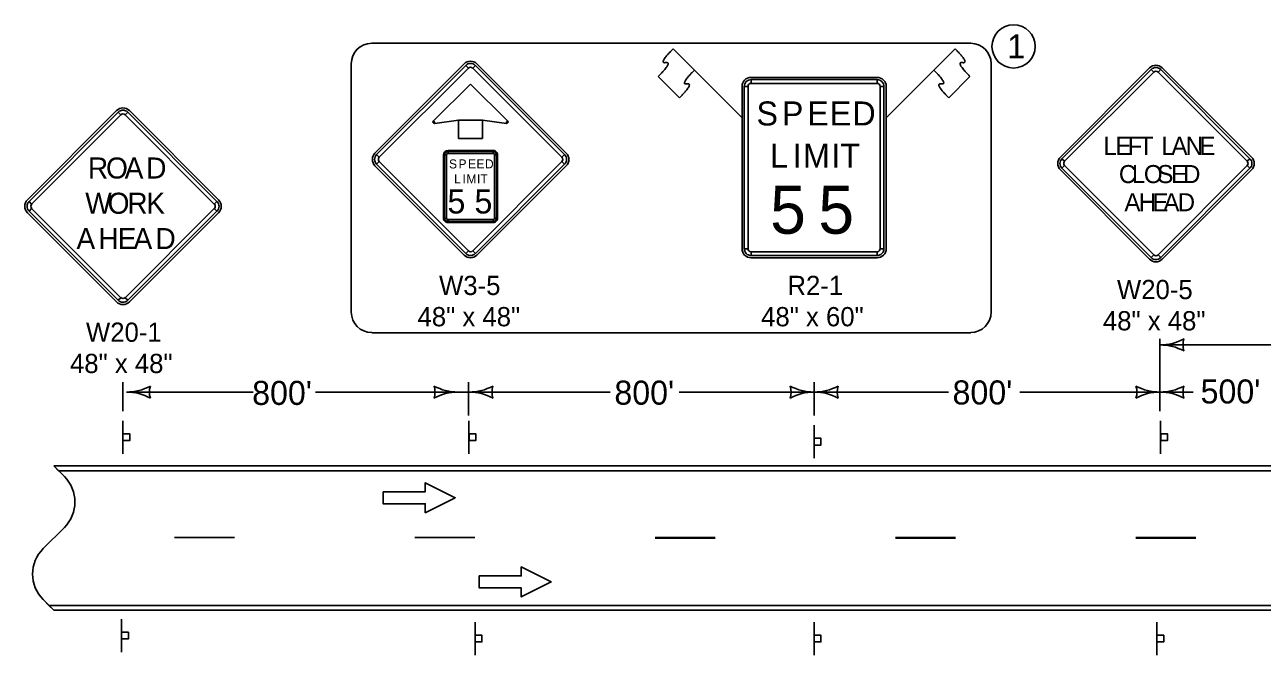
# Model space of a CAD drawing. Extents: x 10133 to 2270741, y 5363 to 1733450.
# Drawn here: x 24538 to 25567, y 6634 to 7159 of the extents above; entities that cross this region are included whole.
import ezdxf

# ---------------------------------------------------------------- set-up
doc = ezdxf.new("R2010")
doc.units = 0
for name, color, linetype in [('dsnNonPlotable', 7, 'Continuous'), ('dsnShtPlotShapeBatchPrint', 7, 'Continuous'), ('dsnStdBorder', 7, 'Continuous'), ('Level 12', 7, 'Continuous'), ('Level 2', 7, 'Continuous')]:
    doc.layers.add(name, color=color, linetype=linetype)

msp = doc.modelspace()

# ---------------------------------------------------------------- linework, layer by layer
at = {"layer": 'dsnNonPlotable'}
for p, q in [((24570.6, 6783), (24561.8, 6791.8)), ((24565.8, 6787.8), (26174.1, 6787.8)), ((24553, 6723), (24570.6, 6740.6)), ((24561.8, 6671.8), (24553, 6680.6)), ((24557.8, 6675.8), (26586.2, 6675.8))]:
    msp.add_line(p, q, dxfattribs=at)
for points in [[(24662.2, 6732.2), (24712.2, 6732.2)], [(24862.2, 6732.2), (24912.1, 6732.2)], [(25062.1, 6732.2), (25112.1, 6732.2)], [(25062.1, 6731.8), (25112.1, 6731.8)], [(25262.1, 6732.2), (25312.1, 6732.2)], [(25262.1, 6731.8), (25312.1, 6731.8)], [(25462.1, 6732.2), (25512.1, 6732.2)], [(25462.1, 6731.8), (25512.1, 6731.8)]]:
    msp.add_lwpolyline(points, dxfattribs=at)
for centre, start, end in [((24549.4, 6761.8), 315, 45), ((24574.2, 6701.8), 135, 225)]:
    msp.add_arc(centre, 30, start, end, dxfattribs=at)
at = {"layer": 'dsnShtPlotShapeBatchPrint'}
msp.add_circle((25360.5, 7140.7), 18, dxfattribs=at)
at = {"layer": 'dsnStdBorder'}
for p, q in [((25134.5, 7081.4), (25077.2, 7138.7)), ((25077.2, 7138.7), (25094.9, 7121)), ((25254.5, 7081.4), (25311.8, 7138.7)), ((25311.8, 7138.7), (25294.1, 7121)), ((24903.3, 7126.2), (24829.1, 7052)), ((24988.2, 7052), (24913.9, 7126.2)), ((24904.6, 7124.9), (24906.8, 7122.7)), ((24910.4, 7122.7), (24912.6, 7124.9)), ((25064.8, 7115.7), (25082.5, 7098)), ((25082.5, 7098), (25064.8, 7115.7)), ((25324.2, 7115.7), (25306.5, 7098)), ((25306.5, 7098), (25324.2, 7115.7)), ((25473.6, 7122.8), (25399.4, 7048.6)), ((25474.9, 7121.5), (25477.1, 7119.3)), ((25480.7, 7119.3), (25482.9, 7121.5)), ((25558.5, 7048.6), (25484.2, 7122.8)), ((25134.5, 7107.4), (25134.5, 6972.4)), ((25136.4, 7107.4), (25139.5, 7107.4)), ((25247, 7114.9), (25142, 7114.9)), ((25142, 7109.9), (25142, 7113.1)), ((25247, 7113.1), (25247, 7109.9)), ((25249.5, 7107.4), (25252.6, 7107.4)), ((25254.5, 6972.4), (25254.5, 7107.4)), ((24614.1, 7087.3), (24539.9, 7013)), ((24615.4, 7085.9), (24617.6, 7083.7)), ((24621.2, 7083.7), (24623.4, 7085.9)), ((24699, 7013), (24624.7, 7087.3)), ((24878.6, 7077.9), (24877.7, 7078.8)), ((24878.8, 7076.7), (24878.6, 7077.9)), ((24938.6, 7077.9), (24938.5, 7076.7)), ((24939.5, 7078.8), (24938.6, 7077.9)), ((24927.4, 7054.2), (24889.9, 7054.2)), ((24832.6, 7048.5), (24830.4, 7050.7)), ((24830.4, 7042.7), (24832.6, 7044.9)), ((24886.1, 7050.4), (24886.1, 6997.9)), ((24887, 7050.4), (24888.6, 7050.4)), ((24889.9, 7051.7), (24889.9, 7053.2)), ((24927.4, 7053.2), (24927.4, 7051.7)), ((24928.6, 7050.4), (24930.2, 7050.4)), ((24931.1, 6997.9), (24931.1, 7050.4)), ((24986.8, 7050.7), (24984.6, 7048.5)), ((24984.6, 7044.9), (24986.8, 7042.7)), ((25402.9, 7045.1), (25400.7, 7047.3)), ((25557.1, 7047.3), (25554.9, 7045.1)), ((24829.1, 7041.4), (24903.3, 6967.1)), ((24913.9, 6967.1), (24988.2, 7041.4)), ((25399.4, 7038), (25473.6, 6963.7)), ((25400.7, 7039.3), (25402.9, 7041.5)), ((25484.2, 6963.7), (25558.5, 7038)), ((25554.9, 7041.5), (25557.1, 7039.3)), ((24539.9, 7002.4), (24614.1, 6928.2)), ((24543.4, 7009.5), (24541.2, 7011.7)), ((24541.2, 7003.7), (24543.4, 7005.9)), ((24624.7, 6928.2), (24699, 7002.4)), ((24697.6, 7011.7), (24695.4, 7009.5)), ((24695.4, 7005.9), (24697.6, 7003.7)), ((24888.6, 6997.9), (24887, 6997.9)), ((24889.9, 6995.1), (24889.9, 6996.7)), ((24889.9, 6994.2), (24927.4, 6994.2)), ((24927.4, 6996.7), (24927.4, 6995.1)), ((24930.2, 6997.9), (24928.6, 6997.9)), ((25139.5, 6972.4), (25136.4, 6972.4)), ((25252.6, 6972.4), (25249.5, 6972.4)), ((24906.8, 6970.7), (24904.6, 6968.5)), ((24912.6, 6968.5), (24910.4, 6970.7)), ((25142, 6966.8), (25142, 6969.9)), ((25142, 6964.9), (25247, 6964.9)), ((25247, 6969.9), (25247, 6966.8)), ((25477.1, 6967.3), (25474.9, 6965.1)), ((25482.9, 6965.1), (25480.7, 6967.3)), ((24617.6, 6931.7), (24615.4, 6929.5)), ((24623.4, 6929.5), (24621.2, 6931.7)), ((24619.4, 6829.3), (24619.4, 6801.8)), ((24907.3, 6829.3), (24907.3, 6801.8)), ((25482.8, 6829.3), (25482.8, 6801.8)), ((25194.5, 6825.6), (25194.5, 6798.1)), ((24618.1, 6664.4), (24618.1, 6636.9)), ((24912.4, 6661.8), (24912.4, 6634.3)), ((25194.5, 6661.8), (25194.5, 6634.3)), ((25479.7, 6661.8), (25479.7, 6634.3))]:
    msp.add_line(p, q, dxfattribs=at)
for points in [[(24826.4, 7143.3), (25324.8, 7143.3)], [(24809.4, 6919.7), (24809.4, 7126.3)], [(25341.9, 7126.3), (25341.9, 6919.7)], [(25324.8, 6902.6), (24826.4, 6902.6)], [(24835.9, 6770.3), (24835.9, 6760.3), (24870.9, 6760.3), (24870.9, 6752.8), (24895.9, 6765.3), (24870.9, 6777.8), (24870.9, 6770.3), (24835.9, 6770.3)], [(24915.8, 6700.3), (24915.8, 6690.3), (24950.8, 6690.3), (24950.8, 6682.8), (24975.8, 6695.3), (24950.8, 6707.8), (24950.8, 6700.3), (24915.8, 6700.3)]]:
    msp.add_lwpolyline(points, dxfattribs=at)
for points in [[(24904.6, 7124.9), (24830.4, 7050.7), (24832.6, 7048.5), (24906.8, 7122.7), (24904.6, 7124.9)], [(24986.8, 7050.7), (24912.6, 7124.9), (24910.4, 7122.7), (24984.6, 7048.5), (24986.8, 7050.7)], [(25474.9, 7121.5), (25400.7, 7047.3), (25402.9, 7045.1), (25477.1, 7119.3), (25474.9, 7121.5)], [(25557.1, 7047.3), (25482.9, 7121.5), (25480.7, 7119.3), (25554.9, 7045.1), (25557.1, 7047.3)], [(24908.6, 7109.2), (24877.7, 7078.8), (24878.6, 7077.9), (24878.8, 7076.7), (24898.6, 7079.2), (24918.6, 7079.2), (24938.5, 7076.7), (24938.6, 7077.9), (24939.5, 7078.8), (24908.6, 7109.2)], [(25136.4, 7107.4), (25136.4, 6972.4), (25139.5, 6972.4), (25139.5, 7107.4), (25136.4, 7107.4)], [(25247, 7113.1), (25142, 7113.1), (25142, 7109.9), (25247, 7109.9), (25247, 7113.1)], [(25252.6, 6972.4), (25252.6, 7107.4), (25249.5, 7107.4), (25249.5, 6972.4), (25252.6, 6972.4)], [(24615.4, 7085.9), (24541.2, 7011.7), (24543.4, 7009.5), (24617.6, 7083.7), (24615.4, 7085.9)], [(24697.6, 7011.7), (24623.4, 7085.9), (24621.2, 7083.7), (24695.4, 7009.5), (24697.6, 7011.7)], [(24918.6, 7064.2), (24898.6, 7064.2), (24898.6, 7079.2), (24918.6, 7079.2), (24918.6, 7064.2)], [(24830.4, 7042.7), (24904.6, 6968.5), (24906.8, 6970.7), (24832.6, 7044.9), (24830.4, 7042.7)], [(24887, 7050.4), (24887, 6997.9), (24888.6, 6997.9), (24888.6, 7050.4), (24887, 7050.4)], [(24927.4, 7053.2), (24889.9, 7053.2), (24889.9, 7051.7), (24927.4, 7051.7), (24927.4, 7053.2)], [(24912.6, 6968.5), (24986.8, 7042.7), (24984.6, 7044.9), (24910.4, 6970.7), (24912.6, 6968.5)], [(24930.2, 6997.9), (24930.2, 7050.4), (24928.6, 7050.4), (24928.6, 6997.9), (24930.2, 6997.9)], [(25400.7, 7039.3), (25474.9, 6965.1), (25477.1, 6967.3), (25402.9, 7041.5), (25400.7, 7039.3)], [(25482.9, 6965.1), (25557.1, 7039.3), (25554.9, 7041.5), (25480.7, 6967.3), (25482.9, 6965.1)], [(24541.2, 7003.7), (24615.4, 6929.5), (24617.6, 6931.7), (24543.4, 7005.9), (24541.2, 7003.7)], [(24623.4, 6929.5), (24697.6, 7003.7), (24695.4, 7005.9), (24621.2, 6931.7), (24623.4, 6929.5)], [(24889.9, 6995.1), (24927.4, 6995.1), (24927.4, 6996.7), (24889.9, 6996.7), (24889.9, 6995.1)], [(25142, 6966.8), (25247, 6966.8), (25247, 6969.9), (25142, 6969.9), (25142, 6966.8)], [(24619.4, 6812.9), (24619.4, 6818.5), (24625.1, 6818.5), (24625.1, 6812.9)], [(24907.4, 6812.9), (24907.4, 6818.5), (24913, 6818.5), (24913, 6812.9)], [(25482.9, 6812.9), (25482.9, 6818.5), (25488.5, 6818.5), (25488.5, 6812.9)], [(25194.6, 6809.1), (25194.6, 6814.8), (25200.2, 6814.8), (25200.2, 6809.1)], [(24618.2, 6647.9), (24618.2, 6653.5), (24623.9, 6653.5), (24623.9, 6647.9)], [(24912.5, 6645.4), (24912.5, 6651), (24918.1, 6651), (24918.1, 6645.4)], [(25194.6, 6645.4), (25194.6, 6651), (25200.2, 6651), (25200.2, 6645.4)], [(25479.8, 6645.4), (25479.8, 6651), (25485.4, 6651), (25485.4, 6645.4)]]:
    msp.add_lwpolyline(points, close=True, dxfattribs=at)
for centre, radius, start, end in [((24826.4, 7126.3), 17, 90, 180), ((25324.8, 7126.3), 17, 0, 90), ((24908.6, 7120.9), 7.5, 45, 134.9997), ((24908.6, 7120.9), 5.62, 45, 134.9997), ((24908.6, 7120.9), 2.5, 45, 134.9997), ((25478.9, 7117.5), 7.5, 45, 134.9997), ((25478.9, 7117.5), 5.62, 45, 134.9997), ((25478.9, 7117.5), 2.5, 45, 134.9997), ((25142, 7107.4), 7.5, 90.0002, 179.9998), ((25142, 7107.4), 5.62, 90.0002, 179.9998), ((25142, 7107.4), 2.5, 90.0002, 179.9998), ((25247, 7107.4), 7.5, 0, 90.0002), ((25247, 7107.4), 5.62, 0, 90.0002), ((25247, 7107.4), 2.5, 0, 90.0002), ((24619.4, 7082), 7.5, 45, 134.9997), ((24619.4, 7082), 5.62, 45, 134.9997), ((24619.4, 7082), 2.5, 45, 134.9997), ((24878.6, 7077.9), 1.25, 134.9997, 277.1529), ((24938.6, 7077.9), 1.25, 262.8473, 44.9998), ((24889.9, 7050.4), 3.75, 90.0002, 179.9998), ((24927.4, 7050.4), 3.75, 0, 90.0002), ((24834.4, 7046.7), 7.5, 134.9997, 225), ((24834.4, 7046.7), 5.62, 134.9997, 225), ((24834.4, 7046.7), 2.5, 134.9997, 225), ((24889.9, 7050.4), 2.81, 90.0002, 179.9998), ((24889.9, 7050.4), 1.25, 90.0002, 179.9998), ((24927.4, 7050.4), 2.81, 0, 90.0002), ((24927.4, 7050.4), 1.25, 0, 90.0002), ((24982.9, 7046.7), 2.5, 315.0002, 44.9998), ((24982.9, 7046.7), 5.62, 315.0002, 44.9998), ((24982.9, 7046.7), 7.5, 315.0002, 44.9998), ((25404.7, 7043.3), 7.5, 134.9997, 225), ((25404.7, 7043.3), 5.62, 134.9997, 225), ((25404.7, 7043.3), 2.5, 134.9997, 225), ((25553.2, 7043.3), 2.5, 315.0002, 44.9998), ((25553.2, 7043.3), 5.62, 315.0002, 44.9998), ((25553.2, 7043.3), 7.5, 315.0002, 44.9998), ((24545.2, 7007.7), 7.5, 134.9997, 225), ((24693.7, 7007.7), 7.5, 315.0002, 44.9998), ((24545.2, 7007.7), 5.62, 134.9997, 225), ((24545.2, 7007.7), 2.5, 134.9997, 225), ((24693.7, 7007.7), 2.5, 315.0002, 44.9998), ((24693.7, 7007.7), 5.62, 315.0002, 44.9998), ((24889.9, 6997.9), 3.75, 179.9998, 270.0001), ((24889.9, 6997.9), 2.81, 179.9998, 270.0001), ((24889.9, 6997.9), 1.25, 179.9998, 270.0001), ((24927.4, 6997.9), 3.75, 270.0001, 0.0003), ((24927.4, 6997.9), 2.81, 270.0001, 0.0003), ((24927.4, 6997.9), 1.25, 270.0001, 0.0003), ((25142, 6972.4), 7.5, 179.9998, 270.0001), ((25142, 6972.4), 5.62, 179.9998, 270.0001), ((25142, 6972.4), 2.5, 179.9998, 270.0001), ((25247, 6972.4), 7.5, 270.0001, 0.0003), ((25247, 6972.4), 5.62, 270.0001, 0.0003), ((25247, 6972.4), 2.5, 270.0001, 0.0003), ((24908.6, 6972.4), 7.5, 225, 315.0002), ((24908.6, 6972.4), 5.62, 225, 315.0002), ((24908.6, 6972.4), 2.5, 225, 315.0002), ((25478.9, 6969), 7.5, 225, 315.0002), ((25478.9, 6969), 5.62, 225, 315.0002), ((25478.9, 6969), 2.5, 225, 315.0002), ((24619.4, 6933.5), 2.5, 225, 315.0002), ((24619.4, 6933.5), 7.5, 225, 315.0002), ((24619.4, 6933.5), 5.62, 225, 315.0002), ((24826.4, 6919.7), 17, 180, 270), ((25324.8, 6919.7), 17, 270, 0)]:
    msp.add_arc(centre, radius, start, end, dxfattribs=at)
for points in [[(25077.2, 7138.7), (25064.8, 7126.3), (25077.2, 7128.1), (25064.8, 7115.7)], [(25064.8, 7115.7), (25077.2, 7128.1), (25064.8, 7126.3), (25077.2, 7138.7)], [(25311.8, 7138.7), (25324.2, 7126.3), (25311.8, 7128.1), (25324.2, 7115.7)], [(25324.2, 7115.7), (25311.8, 7128.1), (25324.2, 7126.3), (25311.8, 7138.7)], [(25094.9, 7121), (25082.5, 7108.6), (25094.8, 7110.4), (25082.5, 7098)], [(25094.9, 7121), (25082.5, 7108.6), (25094.8, 7110.4), (25082.5, 7098)], [(25294.1, 7121), (25306.5, 7108.6), (25294.1, 7110.4), (25306.5, 7098)], [(25294.1, 7121), (25306.5, 7108.6), (25294.1, 7110.4), (25306.5, 7098)]]:
    msp.add_open_spline(points, degree=2, dxfattribs=at)
at = {"layer": 'Level 12'}
for p, q in [((25482.1, 6892.4), (25602.8, 6892.4)), ((25482.3, 6837.3), (25482.3, 6897.4)), ((24619.4, 6837.3), (24619.4, 6861.3)), ((24906.9, 6833.6), (24906.9, 6861.3)), ((25194.5, 6833.6), (25194.5, 6861.3)), ((24727.6, 6853.2), (24622.2, 6853.2)), ((24779.5, 6853.2), (24906.9, 6853.2)), ((25024.7, 6853.2), (24906.9, 6853.2)), ((25082.1, 6853.2), (25194.5, 6853.2)), ((25306.3, 6853.2), (25194.5, 6853.2)), ((25365.7, 6853.2), (25482.1, 6853.2)), ((25482.9, 6853.2), (25510, 6853.2))]:
    msp.add_line(p, q, dxfattribs=at)
for centre, radius, start, end in [((25482.3, 6934.9), 42.5, 270, 298.0725), ((25482.3, 6849.9), 42.5, 61.9275, 90), ((25517.9, 6892.4), 16.4, 162.2666, 197.7334), ((24622.2, 6895.7), 42.5, 270, 298.0725), ((24657.8, 6853.2), 16.4, 162.2666, 197.7334), ((24862.6, 6853.2), 16.4, 342.2666, 17.7334), ((24898.2, 6895.7), 42.5, 241.9275, 270), ((24907.3, 6895.7), 42.5, 270, 298.0725), ((24942.9, 6853.2), 16.4, 162.2666, 197.7334), ((25158.9, 6853.2), 16.4, 342.2666, 17.7334), ((25194.5, 6895.7), 42.5, 241.9275, 270), ((25194.5, 6895.7), 42.5, 270, 298.0725), ((25230.1, 6853.2), 16.4, 162.2666, 197.7334), ((25446.7, 6853.2), 16.4, 342.2666, 17.7334), ((25482.3, 6895.7), 42.5, 241.9275, 270), ((25482.3, 6895.7), 42.5, 270, 298.0725), ((25517.9, 6853.2), 16.4, 162.2666, 197.7334), ((24622.2, 6810.7), 42.5, 61.9275, 90), ((24898.2, 6810.7), 42.5, 90, 118.0725), ((24907.3, 6810.7), 42.5, 61.9275, 90), ((25194.5, 6810.7), 42.5, 90, 118.0725), ((25194.5, 6810.7), 42.5, 61.9275, 90), ((25482.3, 6810.7), 42.5, 90, 118.0725), ((25482.3, 6810.7), 42.5, 61.9275, 90)]:
    msp.add_arc(centre, radius, start, end, dxfattribs=at)
at = {"layer": 'Level 2'}
for p, q in [((25606.3, 6791.8), (24561.8, 6791.8)), ((24561.8, 6791.8), (24570.6, 6783)), ((25598.9, 6791.8), (24561.8, 6791.8)), ((24565.8, 6787.8), (25598.9, 6787.8)), ((24570.6, 6740.6), (24553, 6723)), ((24553, 6680.6), (24557.8, 6675.8)), ((26353.4, 6675.8), (24557.8, 6675.8)), ((24557.8, 6675.8), (24561.8, 6671.8)), ((24557.8, 6675.8), (25775, 6675.8)), ((24561.8, 6671.8), (26380.1, 6671.8)), ((24561.8, 6671.8), (26351.6, 6671.8))]:
    msp.add_line(p, q, dxfattribs=at)
for points in [[(24561.8, 6791.8), (24565.8, 6787.8), (24565.8, 6787.8)], [(24557.8, 6675.8), (24557.8, 6675.8)], [(24557.8, 6675.8), (24557.8, 6675.8)]]:
    msp.add_lwpolyline(points, dxfattribs=at)
for centre, start, end in [((24549.4, 6761.8), 315, 45), ((24574.2, 6701.8), 135, 225)]:
    msp.add_arc(centre, 30, start, end, dxfattribs=at)

# ---------------------------------------------------------------- texts
at = {"layer": 'dsnShtPlotShapeBatchPrint'}
msp.add_text('1', height=20, dxfattribs=at).set_placement((25355.3, 7130.7))
at = {"layer": 'dsnStdBorder'}
for s, height, p in [('S', 20, (25146.6, 7074.9)), ('P', 20, (25167.7, 7074.9)), ('E', 20, (25188.8, 7074.9)), ('E', 20, (25207.6, 7074.9)), ('D', 20, (25226.4, 7074.9)), ('L', 15, (25435.3, 7050.5)), ('E', 15, (25445.3, 7050.5)), ('F', 15, (25455.4, 7050.5)), ('T', 15, (25464.6, 7050.5)), ('L', 15, (25483.4, 7050.5)), ('A', 15, (25491.8, 7050.5)), ('N', 15, (25503.7, 7050.5)), ('E', 15, (25515, 7050.5)), ('L', 20, (25157.9, 7039.9)), ('I', 20, (25176.7, 7039.9)), ('M', 20, (25185.3, 7039.9)), ('I', 20, (25208.9, 7039.9)), ('T', 20, (25216.4, 7039.9)), ('R', 17.5, (24590.2, 7030.8)), ('O', 17.5, (24605.3, 7030.8)), ('A', 17.5, (24620.8, 7030.8)), ('D', 17.5, (24638.7, 7030.8)), ('S', 7.5, (24890.7, 7039.2)), ('P', 7.5, (24898.6, 7039.2)), ('E', 7.5, (24906.5, 7039.2)), ('E', 7.5, (24913.5, 7039.2)), ('D', 7.5, (24920.6, 7039.2)), ('L', 7.5, (24894.9, 7026.7)), ('I', 7.5, (24901.9, 7026.7)), ('M', 7.5, (24905.2, 7026.7)), ('I', 7.5, (24914, 7026.7)), ('T', 7.5, (24916.8, 7026.7)), ('C', 15, (25448.1, 7027)), ('L', 15, (25458.9, 7027)), ('O', 15, (25468.9, 7027)), ('S', 15, (25480.1, 7027)), ('E', 15, (25491.5, 7027)), ('D', 15, (25501.5, 7027)), ('5', 40, (25157.9, 6984.9)), ('5', 40, (25198, 6984.9)), ('W', 17.5, (24588, 7001.5)), ('O', 17.5, (24606.6, 7001.5)), ('R', 17.5, (24623, 7001.5)), ('K', 17.5, (24638.8, 7001.5)), ('5', 20, (24889.4, 7001.7)), ('5', 20, (24911.9, 7001.7)), ('A', 15, (25452.7, 7003.6)), ('H', 15, (25464.6, 7003.6)), ('E', 15, (25475.9, 7003.6)), ('A', 15, (25485.1, 7003.6)), ('D', 15, (25497, 7003.6)), ('A', 17.5, (24580.7, 6972.1)), ('H', 17.5, (24598.9, 6972.1)), ('E', 17.5, (24615.1, 6972.1)), ('A', 17.5, (24628.2, 6972.1)), ('D', 17.5, (24646.4, 6972.1)), ('W3-5', 16, (24882.4, 6933.9)), ('R2-1', 16, (25172.3, 6933.9)), ('W20-5', 16, (25446.5, 6930.5)), ('48" x 48"', 16, (24864.5, 6907.9)), ('48" x 60"', 16, (25150.4, 6907.9)), ('48" x 48"', 16, (25434.8, 6904.5)), ('W20-1', 16, (24588.6, 6895)), ('48" x 48"', 16, (24575.3, 6869))]:
    msp.add_text(s, height=height, dxfattribs=at).set_placement(p)
at = {"layer": 'Level 12'}
for s, p in [("800'", (24726.9, 6842.5)), ("800'", (25028.3, 6842.7)), ("800'", (25309.7, 6842.9)), ("500'", (25516.1, 6843.7))]:
    msp.add_text(s, height=20, dxfattribs=at).set_placement(p)

doc.saveas('drawing.dxf')
